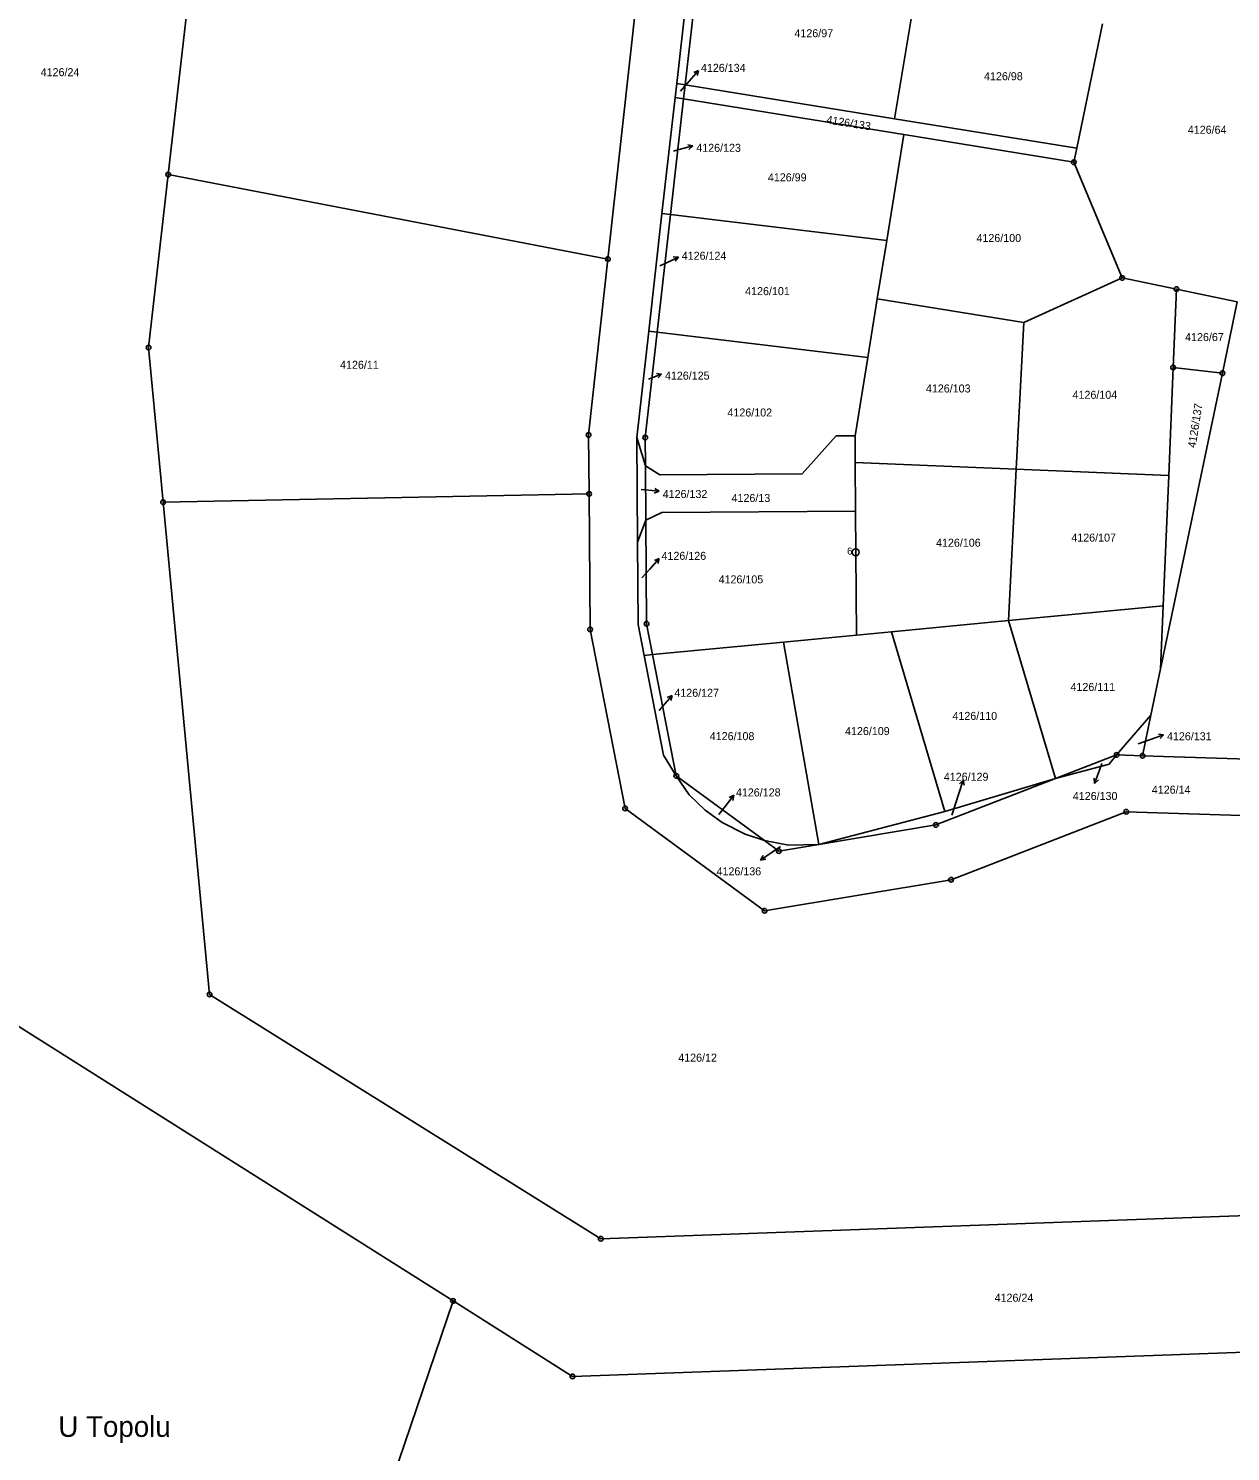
# Model space of a CAD drawing. Extents: x -733394 to -722299, y -1082822 to -1075049.
# Drawn here: x -729564.2 to -729308.9, y -1081571.9 to -1081269.6 of the extents above; entities that cross this region are included whole.
import ezdxf

# ---------------------------------------------------------------- set-up
doc = ezdxf.new("R2010")
doc.units = 0
for name, color, linetype in [('Hranice parcel', 7, 'Continuous'), ('Parcelní čísla', 7, 'Continuous'), ('Pop  PČ popisy', 7, 'Continuous'), ('Značky bodu BP', 7, 'Continuous')]:
    doc.layers.add(name, color=color, linetype=linetype)

msp = doc.modelspace()

# ---------------------------------------------------------------- linework, layer by layer
at = {"layer": 'Hranice parcel'}
for p, q in [((-729524.54, -1081212.42), (-729534.57, -1081300.68)), ((-729441.15, -1081318.63), (-729431.71, -1081232.65)), ((-729426.54, -1081281.31), (-729423.51, -1081254.49)), ((-729421.72, -1081254.7), (-729424.76, -1081281.6)), ((-729380.26, -1081288.81), (-729375.53, -1081260.13)), ((-729336.1, -1081268.67), (-729341.57, -1081295.08)), ((-729426.88, -1081284.31), (-729426.54, -1081281.31)), ((-729426.54, -1081281.31), (-729424.76, -1081281.6)), ((-729429.67, -1081308.96), (-729426.88, -1081284.31)), ((-729425.1, -1081284.6), (-729426.88, -1081284.31)), ((-729424.76, -1081281.6), (-729425.1, -1081284.6)), ((-729424.76, -1081281.6), (-729380.26, -1081288.81)), ((-729425.1, -1081284.6), (-729427.88, -1081309.18)), ((-729378.26, -1081292.2), (-729425.1, -1081284.6)), ((-729380.26, -1081288.81), (-729341.57, -1081295.08)), ((-729381.92, -1081314.72), (-729378.26, -1081292.2)), ((-729342.18, -1081298.05), (-729378.26, -1081292.2)), ((-729341.57, -1081295.08), (-729342.18, -1081298.05)), ((-729342.18, -1081298.05), (-729331.94, -1081322.63)), ((-729534.57, -1081300.68), (-729441.15, -1081318.63)), ((-729432.49, -1081333.95), (-729429.67, -1081308.96)), ((-729427.88, -1081309.18), (-729430.71, -1081334.17)), ((-729429.67, -1081308.96), (-729427.88, -1081309.18)), ((-729427.88, -1081309.18), (-729381.92, -1081314.72)), ((-729381.92, -1081314.72), (-729383.93, -1081327.05)), ((-729352.81, -1081332.11), (-729331.94, -1081322.63)), ((-729331.94, -1081322.63), (-729320.39, -1081325.02)), ((-729320.39, -1081325.02), (-729321.09, -1081341.64)), ((-729320.39, -1081325.02), (-729307.46, -1081327.69)), ((-729385.96, -1081339.56), (-729383.93, -1081327.05)), ((-729383.93, -1081327.05), (-729352.81, -1081332.11)), ((-729307.46, -1081327.69), (-729310.63, -1081342.87)), ((-729354.41, -1081363.25), (-729352.81, -1081332.11)), ((-729435.04, -1081356.52), (-729432.49, -1081333.95)), ((-729432.49, -1081333.95), (-729430.71, -1081334.17)), ((-729430.71, -1081334.17), (-729385.96, -1081339.56)), ((-729388.66, -1081356.16), (-729385.96, -1081339.56)), ((-729322.03, -1081364.59), (-729321.09, -1081341.64)), ((-729321.09, -1081341.64), (-729310.63, -1081342.87)), ((-729310.63, -1081342.87), (-729323.74, -1081405.66)), ((-729434.87, -1081378.74), (-729435.04, -1081356.52)), ((-729435.04, -1081356.52), (-729433.19, -1081362.55)), ((-729388.62, -1081361.84), (-729388.66, -1081356.16)), ((-729433.19, -1081362.55), (-729433.1, -1081374.11)), ((-729388.54, -1081372.16), (-729388.62, -1081361.84)), ((-729388.62, -1081361.84), (-729354.41, -1081363.25)), ((-729356.07, -1081395.41), (-729354.41, -1081363.25)), ((-729354.41, -1081363.25), (-729322.03, -1081364.59)), ((-729323.18, -1081392.27), (-729322.03, -1081364.59)), ((-729535.64, -1081370.27), (-729445.15, -1081368.52)), ((-729433.1, -1081374.11), (-729434.87, -1081378.74)), ((-729388.33, -1081398.5), (-729388.54, -1081372.16)), ((-729356.07, -1081395.41), (-729323.18, -1081392.27)), ((-729323.74, -1081405.66), (-729323.18, -1081392.27)), ((-729380.88, -1081397.79), (-729356.07, -1081395.41)), ((-729346.1, -1081429), (-729356.07, -1081395.41)), ((-729403.84, -1081399.99), (-729388.33, -1081398.5)), ((-729388.33, -1081398.5), (-729380.88, -1081397.79)), ((-729369.59, -1081435.99), (-729380.88, -1081397.79)), ((-729431.65, -1081402.65), (-729403.84, -1081399.99)), ((-729396.36, -1081442.97), (-729403.84, -1081399.99)), ((-729433.45, -1081402.82), (-729431.65, -1081402.65)), ((-729431.65, -1081402.65), (-729426.62, -1081428.41)), ((-729323.74, -1081405.66), (-729325.8, -1081415.54)), ((-729333.09, -1081423.96), (-729325.8, -1081415.54)), ((-729325.8, -1081415.54), (-729327.59, -1081424.13)), ((-729346.1, -1081429), (-729333.09, -1081423.96)), ((-729327.59, -1081424.13), (-729333.09, -1081423.96)), ((-729426.62, -1081428.41), (-729407.87, -1081442.17)), ((-729369.59, -1081435.99), (-729346.1, -1081429)), ((-729396.36, -1081442.97), (-729369.59, -1081435.99))]:
    msp.add_line(p, q, dxfattribs=at)
for points in [[(-729594.79, -1081182.2), (-729585.66, -1081281.78), (-729576.53, -1081381.36), (-729567.4, -1081480.95), (-729474.06, -1081539.95)], [(-729534.57, -1081300.68), (-729538.74, -1081337.43), (-729535.64, -1081370.27)], [(-729445.15, -1081368.52), (-729445.25, -1081356), (-729441.15, -1081318.63)], [(-729430.71, -1081334.17), (-729433.24, -1081356.55), (-729433.19, -1081362.55)], [(-729388.66, -1081356.16), (-729392.66, -1081356.2), (-729399.91, -1081364.25), (-729430.12, -1081364.49), (-729433.19, -1081362.55)], [(-729274.57, -1081441.49), (-729291.08, -1081437.29), (-729331.04, -1081436.03), (-729368.27, -1081450.47), (-729407.87, -1081457.05), (-729437.5, -1081435.32), (-729444.93, -1081397.3), (-729445.15, -1081368.52)], [(-729535.64, -1081370.27), (-729525.78, -1081474.82), (-729442.66, -1081526.74), (-729289.62, -1081521.22)], [(-729433.1, -1081374.11), (-729429.68, -1081372.49), (-729388.54, -1081372.16)], [(-729433.1, -1081374.11), (-729432.93, -1081396.08), (-729431.65, -1081402.65)], [(-729433.45, -1081402.82), (-729434.73, -1081396.26), (-729434.87, -1081378.74)], [(-729426.62, -1081428.41), (-729429.32, -1081423.99), (-729433.45, -1081402.82)], [(-729333.09, -1081423.96), (-729334.7, -1081425.9), (-729346.1, -1081429)], [(-729218.4, -1081449.32), (-729249.36, -1081435.53), (-729289.41, -1081425.33), (-729327.59, -1081424.13)], [(-729407.87, -1081442.17), (-729412.02, -1081440.8), (-729416.86, -1081438.31), (-729420.51, -1081435.69), (-729423.87, -1081432.47), (-729426.62, -1081428.41)], [(-729346.1, -1081429), (-729371.46, -1081438.83), (-729396.36, -1081442.97)], [(-729396.36, -1081442.97), (-729404.85, -1081444.38), (-729407.87, -1081442.17)], [(-729407.87, -1081442.17), (-729402.82, -1081443.11), (-729396.36, -1081442.97)], [(-729474.06, -1081539.95), (-729507.39, -1081638.15), (-729357.49, -1081632.74)], [(-729474.06, -1081539.95), (-729448.7, -1081555.98), (-729278.36, -1081549.84)]]:
    msp.add_lwpolyline(points, dxfattribs=at)
at = {"layer": 'Pop  PČ popisy'}
for p, q in [((-729425.72, -1081282.94), (-729423.86, -1081280.83)), ((-729423.86, -1081280.83), (-729421.89, -1081278.56)), ((-729421.89, -1081278.56), (-729422.93, -1081278.99)), ((-729421.89, -1081278.56), (-729422.17, -1081279.65)), ((-729427.22, -1081295.69), (-729426.01, -1081295.37)), ((-729426.01, -1081295.37), (-729423.11, -1081294.59)), ((-729423.11, -1081294.59), (-729424.21, -1081294.37)), ((-729423.11, -1081294.59), (-729423.95, -1081295.34)), ((-729430.11, -1081320.07), (-729428.88, -1081319.49)), ((-729428.88, -1081319.49), (-729426.16, -1081318.22)), ((-729426.16, -1081318.22), (-729427.28, -1081318.19)), ((-729426.16, -1081318.22), (-729426.86, -1081319.1)), ((-729432.55, -1081344.14), (-729429.75, -1081343.06)), ((-729429.75, -1081343.06), (-729430.86, -1081342.96)), ((-729429.75, -1081343.06), (-729430.5, -1081343.89)), ((-729434.07, -1081367.6), (-729433.26, -1081367.67)), ((-729433.26, -1081367.67), (-729430.27, -1081367.93)), ((-729430.27, -1081367.93), (-729431.31, -1081368.34)), ((-729430.27, -1081367.93), (-729431.22, -1081367.34)), ((-729432.26, -1081384.47), (-729430.25, -1081382.24)), ((-729430.25, -1081382.24), (-729431.29, -1081382.65)), ((-729430.25, -1081382.24), (-729430.55, -1081383.32)), ((-729433.92, -1081386.34), (-729432.26, -1081384.47)), ((-729430.27, -1081414.53), (-729429.48, -1081413.61)), ((-729429.48, -1081413.61), (-729427.51, -1081411.34)), ((-729427.51, -1081411.34), (-729428.55, -1081411.77)), ((-729427.51, -1081411.34), (-729427.79, -1081412.43)), ((-729325.92, -1081420.69), (-729323.1, -1081419.66)), ((-729323.1, -1081419.66), (-729324.21, -1081419.54)), ((-729323.1, -1081419.66), (-729323.87, -1081420.48)), ((-729328.48, -1081421.6), (-729325.92, -1081420.69)), ((-729336.23, -1081425.81), (-729336.73, -1081427.18)), ((-729366.6, -1081432.16), (-729365.67, -1081429.31)), ((-729365.67, -1081429.31), (-729366.46, -1081430.1)), ((-729365.67, -1081429.31), (-729365.51, -1081430.41)), ((-729337.76, -1081430), (-729337.88, -1081428.89)), ((-729336.73, -1081427.18), (-729337.76, -1081430)), ((-729337.76, -1081430), (-729336.94, -1081429.23)), ((-729368.1, -1081436.77), (-729366.6, -1081432.16)), ((-729417.62, -1081436.62), (-729416.26, -1081434.88)), ((-729416.26, -1081434.88), (-729414.41, -1081432.52)), ((-729414.41, -1081432.52), (-729415.42, -1081433)), ((-729414.41, -1081432.52), (-729414.63, -1081433.61)), ((-729404.49, -1081443.42), (-729406.24, -1081444.6)), ((-729406.24, -1081444.6), (-729408.73, -1081446.28)), ((-729408.73, -1081446.28), (-729408.18, -1081445.3)), ((-729408.73, -1081446.28), (-729407.62, -1081446.13))]:
    msp.add_line(p, q, dxfattribs=at)
at = {"layer": 'Značky bodu BP'}
for centre, radius in [((-729342.18, -1081298.05), 0.5), ((-729342.18, -1081298.05), 0.0303), ((-729534.57, -1081300.68), 0.5), ((-729534.57, -1081300.68), 0.0303), ((-729441.15, -1081318.63), 0.5), ((-729441.15, -1081318.63), 0.0303), ((-729331.94, -1081322.63), 0.5), ((-729331.94, -1081322.63), 0.0303), ((-729320.39, -1081325.02), 0.5), ((-729320.39, -1081325.02), 0.0303), ((-729538.74, -1081337.43), 0.5), ((-729538.74, -1081337.43), 0.0303), ((-729321.09, -1081341.64), 0.5), ((-729321.09, -1081341.64), 0.0303), ((-729310.63, -1081342.87), 0.5), ((-729310.63, -1081342.87), 0.0303), ((-729445.25, -1081356), 0.5), ((-729445.25, -1081356), 0.0303), ((-729433.24, -1081356.55), 0.5), ((-729433.24, -1081356.55), 0.0303), ((-729445.15, -1081368.52), 0.5), ((-729445.15, -1081368.52), 0.0303), ((-729535.64, -1081370.27), 0.5), ((-729535.64, -1081370.27), 0.0303), ((-729388.53, -1081380.91), 0.75), ((-729388.53, -1081380.91), 0.03), ((-729432.93, -1081396.08), 0.5), ((-729432.93, -1081396.08), 0.0303), ((-729444.93, -1081397.3), 0.5), ((-729444.93, -1081397.3), 0.0303), ((-729333.09, -1081423.96), 0.5), ((-729333.09, -1081423.96), 0.0303), ((-729327.59, -1081424.13), 0.5), ((-729327.59, -1081424.13), 0.0303), ((-729426.62, -1081428.41), 0.5), ((-729426.62, -1081428.41), 0.0303), ((-729437.5, -1081435.32), 0.5), ((-729437.5, -1081435.32), 0.0303), ((-729371.46, -1081438.83), 0.5), ((-729331.04, -1081436.03), 0.5), ((-729331.04, -1081436.03), 0.0303), ((-729371.46, -1081438.83), 0.0303), ((-729404.85, -1081444.38), 0.5), ((-729404.85, -1081444.38), 0.0303), ((-729368.27, -1081450.47), 0.5), ((-729368.27, -1081450.47), 0.0303), ((-729407.87, -1081457.05), 0.5), ((-729407.87, -1081457.05), 0.0303), ((-729525.78, -1081474.82), 0.5), ((-729525.78, -1081474.82), 0.0303), ((-729442.66, -1081526.74), 0.5), ((-729442.66, -1081526.74), 0.0303), ((-729474.06, -1081539.95), 0.5), ((-729474.06, -1081539.95), 0.0303), ((-729448.7, -1081555.98), 0.5), ((-729448.7, -1081555.98), 0.0303)]:
    msp.add_circle(centre, radius, dxfattribs=at)

# ---------------------------------------------------------------- texts
at = {"layer": 'Parcelní čísla'}
for s, p in [('4126/97', (-729401.53, -1081271.51)), ('4126/24', (-729561.65, -1081279.78)), ('4126/134', (-729421.39, -1081278.86)), ('4126/98', (-729361.25, -1081280.64)), ('4126/64', (-729317.97, -1081292.01)), ('4126/123', (-729422.38, -1081295.85)), ('4126/99', (-729407.17, -1081302.12)), ('4126/100', (-729362.86, -1081315.01)), ('4126/124', (-729425.47, -1081318.77)), ('4126/101', (-729412, -1081326.29)), ('4126/67', (-729318.54, -1081336.05)), ('4126/11', (-729498.05, -1081341.94)), ('4126/125', (-729429.04, -1081344.24)), ('4126/103', (-729373.6, -1081346.97)), ('4126/104', (-729342.45, -1081348.31)), ('4126/102', (-729415.76, -1081352.07)), ('4126/132', (-729429.52, -1081369.39)), ('4126/13', (-729414.89, -1081370.23)), ('4126/106', (-729371.45, -1081379.73)), ('4126/107', (-729342.71, -1081378.65)), ('4126/126', (-729429.77, -1081382.52)), ('4126/105', (-729417.64, -1081387.52)), ('4126/127', (-729427.04, -1081411.61)), ('4126/111', (-729342.89, -1081410.37)), ('4126/110', (-729367.96, -1081416.52)), ('4126/108', (-729419.52, -1081420.82)), ('4126/109', (-729390.78, -1081419.74)), ('4126/131', (-729322.39, -1081420.85)), ('4126/129', (-729369.8, -1081429.45)), ('4126/128', (-729413.96, -1081432.77)), ('4126/130', (-729342.39, -1081433.53)), ('4126/14', (-729325.61, -1081432.19)), ('4126/136', (-729418.08, -1081449.54)), ('4126/12', (-729426.21, -1081489.12)), ('4126/24', (-729359.01, -1081540.11))]:
    msp.add_text(s, height=1.7, dxfattribs=at).set_placement(p)
for s, rotation, p in [('4126/133', 351, (-729394.83, -1081289.81)), ('4126/137', 81, (-729316.32, -1081358.81))]:
    msp.add_text(s, height=1.7, rotation=rotation, dxfattribs=at).set_placement(p)
at = {"layer": 'Pop  PČ popisy'}
msp.add_text('U Topolu', height=4.4, dxfattribs=at).set_placement((-729557.9, -1081568.82))
at = {"layer": 'Značky bodu BP'}
msp.add_text('6', height=1.5, dxfattribs=at).set_placement((-729390.34, -1081381.41))

doc.saveas('drawing.dxf')
